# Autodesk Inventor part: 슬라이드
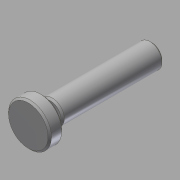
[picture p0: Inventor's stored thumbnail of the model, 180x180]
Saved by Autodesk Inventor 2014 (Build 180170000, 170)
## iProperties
Created: 2015-09
Part Number: 슬라이드
Material: 강철, 연강
Document SubType Name: Modeling
Designer: mduedu
Density: 1 g/cm^3
Appearance: 강철
Author: mduedu
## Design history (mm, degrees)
sketch "스케치1"
  geometry: C1 r 12.5 at (0, 0); 1 further point
  constraints: 1 centre point, 1 coincident
  dimensions: "d0" = 25 diameter of C1
extrude "돌출1" new body sketch "스케치1" distance "d1" = 8; taper "d2" = 0 deg
sketch "스케치2"
  geometry: C1 r 4 at (0, 0); 1 further point
  constraints: 1 centre point, 1 coincident
  dimensions: "d3" = 8 diameter of C1
extrude "돌출2" join sketch "스케치2" distance "d4" = 5; taper "d5" = 0 deg
sketch "스케치3"
  geometry: C1 r 7 at (0, 0); 1 further point
  constraints: 1 centre point, 1 coincident
  dimensions: "d6" = 14 diameter of C1
extrude "돌출3" join sketch "스케치3" distance "d7" = 59; taper "d8" = 0 deg
hole "구멍1" diameter "d11" = 4.134; stored, may be unused: countersink angle "d15" = 90 deg, drill point angle "d17" = 118 deg; dims "d9" = 10, "d10" = 10, "d12" = 9, "d13" = 4, "d14" = 2, "d16" = 12
chamfer "모따기1" distance "d18" = 1; stored, may be unused: second distance "d19" = 2, angle "d20" = 45 deg
node "솔리드1"
